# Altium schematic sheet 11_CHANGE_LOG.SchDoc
size A2; ApprovedBy: DNP; CheckedBy: DNP; Author: DNP; CompanyName: Google LLC; DrawnBy: DNP; Engineer: Bangfei/Michael/Leo; Organization: Google LLC; Address1: 1600 Amphitheatre Parkway; Address2: Mountain View, CA 94043; Address3: DNP; Address4: DNP; DocumentNumber: DNP; Revision: PVT; SheetNumber: 11; SheetTotal: 11; VersionControl_RevNumber: DNP; IsUserConfigurable: DNP
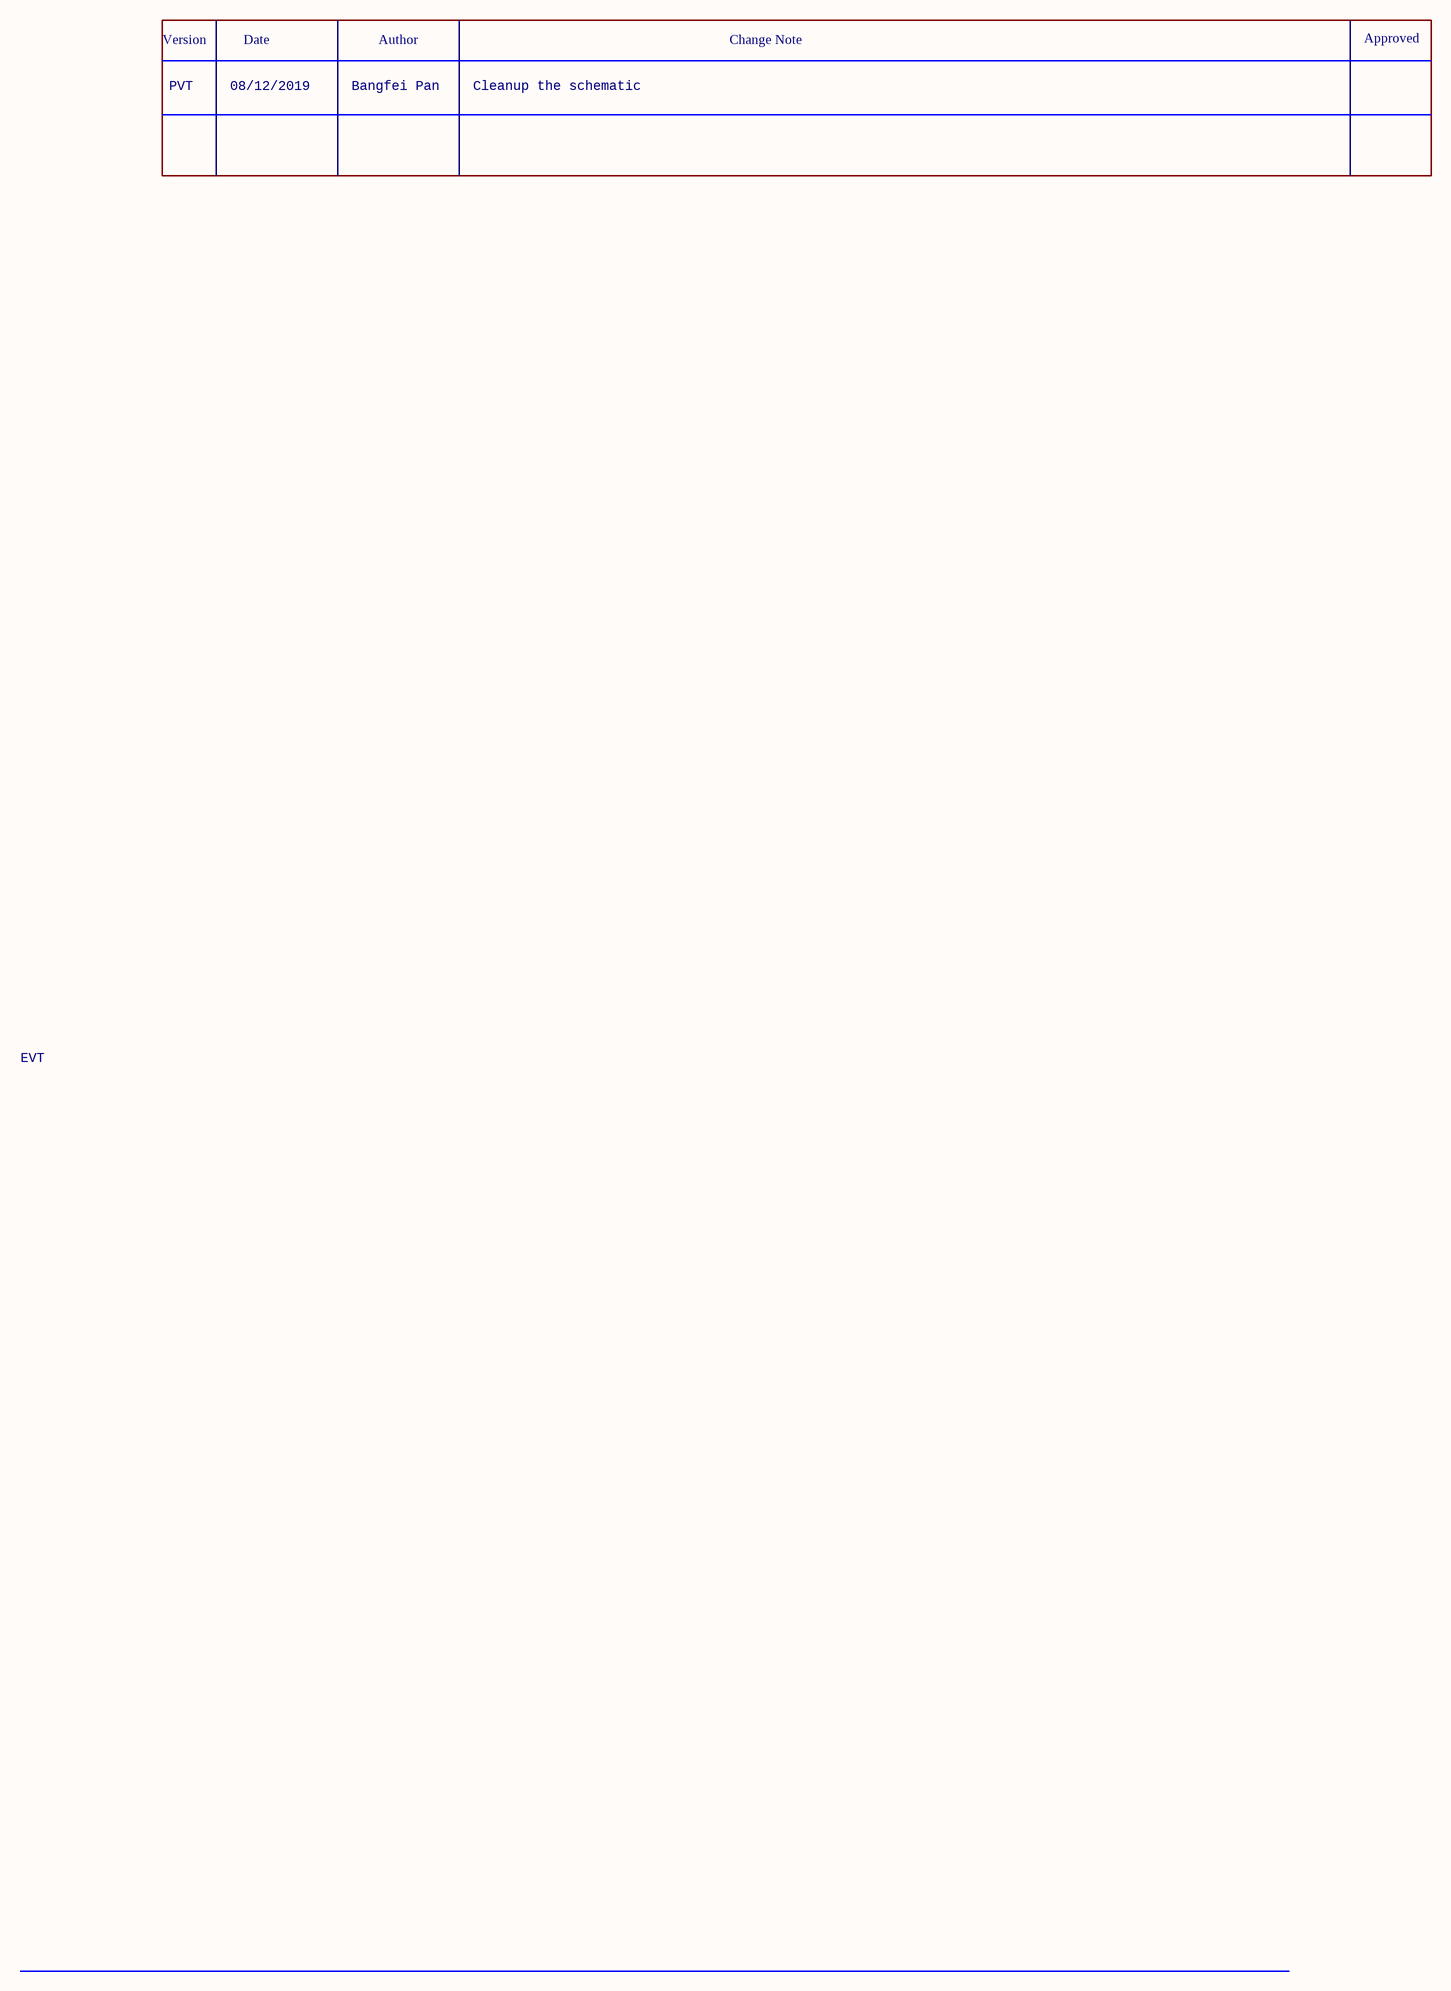
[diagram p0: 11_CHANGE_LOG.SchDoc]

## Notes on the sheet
- Version
- Date
- Author
- Change Note
- Approved
- PVT
- 08/12/2019
- Bangfei Pan
- Cleanup the schematic
- EVT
